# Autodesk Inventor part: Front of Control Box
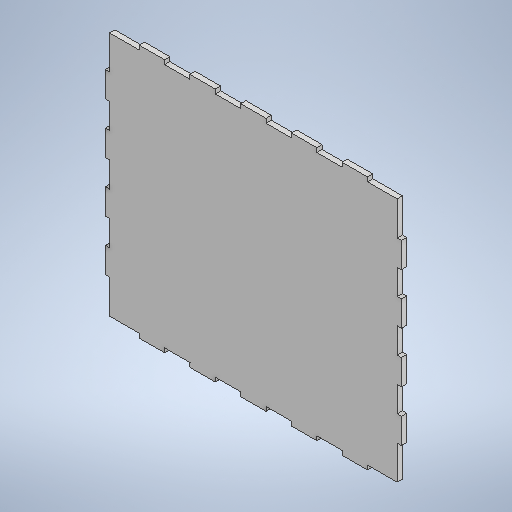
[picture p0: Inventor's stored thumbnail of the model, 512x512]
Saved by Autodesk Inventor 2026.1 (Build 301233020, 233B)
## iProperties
Created: 2026-11
Part Number: Front of Control Box
Material: Generic
Document SubType Name: Modeling
Designer: hp
Density: 1 g/cm^3
Appearance: Default
Author: hp
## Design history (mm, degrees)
sketch "Sketch1"
  geometry: L1 (0, 240)-(280, 240); L2 (280, 240)-(280, 0); L3 (280, 0)-(0, 0); L4 (0, 0)-(0, 240); L5 (152, 0)-(128, 0); L6 (128, 0)-(128, 4); L7 (128, 4)-(152, 4); L8 (152, 4)-(152, 0); L9 (104, 0)-(80, 0); L10 (80, 0)-(80, 4); L11 (80, 4)-(104, 4); L12 (104, 4)-(104, 0); L13 (56, 0)-(32, 0); L14 (32, 0)-(32, 4); L15 (32, 4)-(56, 4); L16 (56, 4)-(56, 0); L17 (200, 0)-(176, 0); L18 (176, 0)-(176, 4); L19 (176, 4)-(200, 4); L20 (200, 4)-(200, 0); L21 (152, 0)-(128, 0); L22 (128, 0)-(128, 4); L23 (128, 4)-(152, 4); L24 (152, 4)-(152, 0); L25 (104, 0)-(80, 0); L26 (80, 0)-(80, 4); L27 (80, 4)-(104, 4); L28 (104, 4)-(104, 0); L29 (248, 0)-(224, 0); L30 (224, 0)-(224, 4); L31 (224, 4)-(248, 4); L32 (248, 4)-(248, 0); L33 (200, 0)-(176, 0); L34 (176, 0)-(176, 4); L35 (176, 4)-(200, 4); L36 (200, 4)-(200, 0); L37 (152, 0)-(128, 0); L38 (128, 0)-(128, 4); L39 (128, 4)-(152, 4); L40 (152, 4)-(152, 0); L41 (280, 120)-(0, 120); L42 (140, 240)-(140, 0); L43 (200, 236)-(200, 240); L44 (200, 240)-(176, 240); L45 (176, 240)-(176, 236); L46 (176, 236)-(200, 236); L47 (152, 236)-(152, 240); L48 (152, 240)-(128, 240); L49 (128, 240)-(128, 236); L50 (128, 236)-(152, 236); L51 (56, 236)-(56, 240); L52 (80, 240)-(80, 236); L53 (80, 236)-(104, 236); L54 (104, 240)-(80, 240); L55 (104, 236)-(104, 240); L56 (56, 240)-(32, 240); L57 (32, 240)-(32, 236); L58 (32, 236)-(56, 236); L59 (224, 236)-(248, 236); L60 (248, 236)-(248, 240); L61 (248, 240)-(224, 240); L62 (224, 240)-(224, 236); L63 (152, 236)-(152, 240); L64 (200, 240)-(176, 240)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; 153 further points
  constraints: 308 end point, 90 symmetric about line, 8 parallel, 6 midpoint, 5 horizontal, 4 perpendicular, 2 vertical, 1 point on line, 3 other
  dimensions: "d8" = 280 distance of L2.end L3.end; "d9" = 240 distance of L1.end L2.end; "d10" = 24 distance of L6.end L7.end; "d11" = 4 distance of L5.end L6.end; "d12" = 48 distance of L5.start L9.start; "d13" = 48 distance of L5.start L17.start; "d14" = 4 distance of L81.end L80.end; "d15" = 24 distance of L80.end L79.end; "d16" = 48 distance of L79.end L83.end; "d17" = 48 distance of L79.end L91.end; "d18" = 4 distance between parallel lines of L1 L151
extrude "Extrusion1" new body sketch "Sketch1" distance "d19" = 5; taper "d20" = 0 deg
body "Solid1"
node "Sketch Rectangular Pattern2" dims "d12" = 48, "d13" = 48
node "Sketch Rectangular Pattern4" dims "d16" = 48, "d17" = 48
